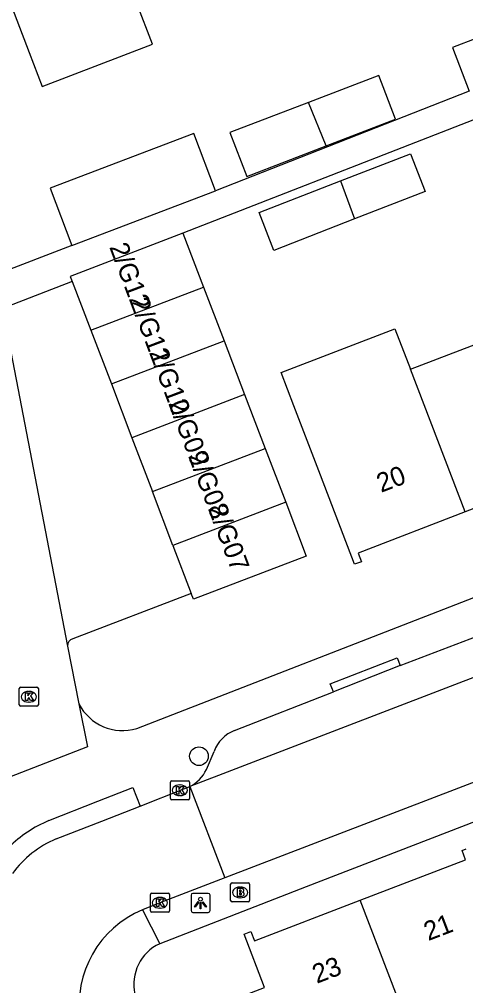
# Model space of a CAD drawing. Extents: x 159265 to 160143, y 383413 to 384319.
# Drawn here: x 159373.8 to 159397.2, y 383766.1 to 383816.8 of the extents above; entities that cross this region are included whole.
import ezdxf

# ---------------------------------------------------------------- set-up
doc = ezdxf.new("R2010")
doc.units = 0
for name, color, linetype in [('IMGEO_Boom', 7, 'Continuous'), ('IMGEO_Brandkraan', 7, 'Continuous'), ('IMGEO_Kolk', 7, 'Continuous'), ('IMGEO_Lichtpunt', 7, 'Continuous'), ('IMGEO_Pand', 7, 'Continuous'), ('IMGEO_Pand_nummerreeks', 7, 'Continuous'), ('IMGEO_Rijbaan_lokaal_open', 7, 'Continuous'), ('IMGEO_Voetpad_open', 7, 'Continuous')]:
    doc.layers.add(name, color=color, linetype=linetype)

msp = doc.modelspace()

# ---------------------------------------------------------------- linework, layer by layer
at = {"layer": 'IMGEO_Boom'}
msp.add_circle((159383.218, 383778.141), 0.489, dxfattribs=at)
at = {"layer": 'IMGEO_Brandkraan'}
for p, q in [((159384.953, 383771.497), (159385.805, 383771.497)), ((159384.878, 383770.571), (159384.878, 383771.423)), ((159385.366, 383771.277), (159385.391, 383771.277)), ((159385.879, 383771.423), (159385.879, 383770.571)), ((159385.805, 383770.497), (159384.953, 383770.497)), ((159385.389, 383770.717), (159385.364, 383770.717))]:
    msp.add_line(p, q, dxfattribs=at)
for points in [[(159384.953, 383771.497), (159385.805, 383771.497)], [(159384.878, 383770.571), (159384.878, 383771.423)], [(159385.226, 383771.197), (159385.226, 383770.797), (159385.439, 383770.797)], [(159385.457, 383771.197), (159385.226, 383771.197)], [(159385.405, 383771.116), (159385.351, 383771.116), (159385.351, 383771.04)], [(159385.351, 383771.04), (159385.404, 383771.04)], [(159385.879, 383771.423), (159385.879, 383770.571)], [(159385.805, 383770.497), (159384.953, 383770.497)], [(159385.413, 383770.964), (159385.351, 383770.964), (159385.351, 383770.883)], [(159385.351, 383770.883), (159385.413, 383770.883)]]:
    msp.add_lwpolyline(points, dxfattribs=at)
for centre, radius, start, end in [((159384.955, 383771.421), 0.0765, 91.552, 178.448), ((159384.955, 383771.421), 0.0765, 91.552, 178.448), ((159385.803, 383771.421), 0.0765, 1.552, 88.448), ((159385.803, 383771.421), 0.0765, 1.552, 88.448), ((159385.406, 383771.078), 0.0379, 267.8285, 90.9355), ((159385.461, 383771.052), 0.145, 59.4692, 91.5367), ((159385.486, 383771.099), 0.0922, 285.5137, 58.1501), ((159385.491, 383770.907), 0.105, 301.3115, 78.989), ((159384.955, 383770.573), 0.0765, 181.552, 268.448), ((159384.955, 383770.573), 0.0765, 181.552, 268.448), ((159385.414, 383770.923), 0.0404, 269.8759, 90.5077), ((159385.445, 383771.048), 0.251, 268.6676, 293.5347), ((159385.803, 383770.573), 0.0765, 271.552, 358.448), ((159385.803, 383770.573), 0.0765, 271.552, 358.448)]:
    msp.add_arc(centre, radius, start, end, dxfattribs=at)
for centre, major_axis, ratio, start_param, end_param in [((159385.365, 383770.997), (-0.387, 0.002), 0.722429, 4.712389, 7.853982), ((159385.39, 383770.997), (-0.39, 0.002), 0.717154, 1.570796, 4.712389)]:
    msp.add_ellipse(centre, major_axis=major_axis, ratio=ratio, start_param=start_param, end_param=end_param, dxfattribs=at)
at = {"layer": 'IMGEO_Kolk'}
for p, q in [((159373.785, 383780.835), (159373.785, 383781.687)), ((159373.86, 383781.761), (159374.712, 383781.761)), ((159374.786, 383781.687), (159374.786, 383780.835)), ((159374.273, 383781.541), (159374.298, 383781.541)), ((159374.712, 383780.761), (159373.86, 383780.761)), ((159374.296, 383780.981), (159374.271, 383780.981)), ((159381.718, 383775.927), (159381.718, 383776.779)), ((159381.793, 383776.853), (159382.645, 383776.853)), ((159382.206, 383776.633), (159382.231, 383776.633)), ((159382.719, 383776.779), (159382.719, 383775.927)), ((159382.229, 383776.073), (159382.204, 383776.073)), ((159382.645, 383775.853), (159381.793, 383775.853)), ((159380.668, 383770.026), (159380.668, 383770.878)), ((159380.743, 383770.952), (159381.595, 383770.952)), ((159381.156, 383770.732), (159381.181, 383770.732)), ((159381.669, 383770.878), (159381.669, 383770.026)), ((159381.179, 383770.172), (159381.154, 383770.172)), ((159381.595, 383769.952), (159380.743, 383769.952))]:
    msp.add_line(p, q, dxfattribs=at)
for points in [[(159373.785, 383780.835), (159373.785, 383781.687)], [(159373.86, 383781.761), (159374.712, 383781.761)], [(159374.786, 383781.687), (159374.786, 383780.835)], [(159374.106, 383781.461), (159374.229, 383781.461), (159374.229, 383781.31), (159374.359, 383781.461), (159374.523, 383781.461), (159374.377, 383781.31), (159374.53, 383781.061), (159374.378, 383781.061), (159374.293, 383781.225), (159374.229, 383781.158), (159374.229, 383781.061), (159374.106, 383781.061), (159374.106, 383781.461)], [(159374.712, 383780.761), (159373.86, 383780.761)], [(159381.718, 383775.927), (159381.718, 383776.779)], [(159381.793, 383776.853), (159382.645, 383776.853)], [(159382.039, 383776.553), (159382.162, 383776.553), (159382.162, 383776.402), (159382.292, 383776.553), (159382.456, 383776.553), (159382.31, 383776.402), (159382.463, 383776.153), (159382.311, 383776.153), (159382.226, 383776.317), (159382.162, 383776.25), (159382.162, 383776.153), (159382.039, 383776.153), (159382.039, 383776.553)], [(159382.719, 383776.779), (159382.719, 383775.927)], [(159382.645, 383775.853), (159381.793, 383775.853)], [(159380.668, 383770.026), (159380.668, 383770.878)], [(159380.743, 383770.952), (159381.595, 383770.952)], [(159380.989, 383770.652), (159381.112, 383770.652), (159381.112, 383770.501), (159381.242, 383770.652), (159381.406, 383770.652), (159381.26, 383770.501), (159381.413, 383770.252), (159381.261, 383770.252), (159381.176, 383770.416), (159381.112, 383770.349), (159381.112, 383770.252), (159380.989, 383770.252), (159380.989, 383770.652)], [(159381.669, 383770.878), (159381.669, 383770.026)], [(159381.595, 383769.952), (159380.743, 383769.952)]]:
    msp.add_lwpolyline(points, dxfattribs=at)
for centre, start, end in [((159373.862, 383781.685), 91.552, 178.448), ((159373.862, 383781.685), 91.552, 178.448), ((159374.71, 383781.685), 1.552, 88.448), ((159374.71, 383781.685), 1.552, 88.448), ((159373.862, 383780.837), 181.552, 268.448), ((159373.862, 383780.837), 181.552, 268.448), ((159374.71, 383780.837), 271.552, 358.448), ((159374.71, 383780.837), 271.552, 358.448), ((159381.795, 383776.777), 91.552, 178.448), ((159381.795, 383776.777), 91.552, 178.448), ((159382.643, 383776.777), 1.552, 88.448), ((159382.643, 383776.777), 1.552, 88.448), ((159381.795, 383775.929), 181.552, 268.448), ((159381.795, 383775.929), 181.552, 268.448), ((159382.643, 383775.929), 271.552, 358.448), ((159382.643, 383775.929), 271.552, 358.448), ((159380.745, 383770.876), 91.552, 178.448), ((159380.745, 383770.876), 91.552, 178.448), ((159381.593, 383770.876), 1.552, 88.448), ((159381.593, 383770.876), 1.552, 88.448), ((159380.745, 383770.028), 181.552, 268.448), ((159380.745, 383770.028), 181.552, 268.448), ((159381.593, 383770.028), 271.552, 358.448), ((159381.593, 383770.028), 271.552, 358.448)]:
    msp.add_arc(centre, 0.0765, start, end, dxfattribs=at)
for centre, major_axis, ratio, start_param, end_param in [((159374.272, 383781.261), (-0.387, 0.002), 0.722429, 4.712389, 7.853982), ((159374.297, 383781.261), (-0.39, 0.002), 0.717154, 1.570796, 4.712389), ((159382.205, 383776.353), (-0.387, 0.002), 0.722429, 4.712389, 7.853982), ((159382.23, 383776.353), (-0.39, 0.002), 0.717154, 1.570796, 4.712389), ((159381.155, 383770.452), (-0.387, 0.002), 0.722429, 4.712389, 7.853982), ((159381.18, 383770.452), (-0.39, 0.002), 0.717154, 1.570796, 4.712389)]:
    msp.add_ellipse(centre, major_axis=major_axis, ratio=ratio, start_param=start_param, end_param=end_param, dxfattribs=at)
at = {"layer": 'IMGEO_Lichtpunt'}
for p, q in [((159382.802, 383770.846), (159382.802, 383770.039)), ((159382.802, 383770.846), (159382.802, 383770.039)), ((159383.704, 383770.941), (159382.896, 383770.941)), ((159383.704, 383770.941), (159382.896, 383770.941)), ((159383.798, 383770.039), (159383.798, 383770.846)), ((159383.798, 383770.039), (159383.798, 383770.846)), ((159382.896, 383769.945), (159383.704, 383769.945)), ((159382.896, 383769.945), (159383.704, 383769.945))]:
    msp.add_line(p, q, dxfattribs=at)
for points in [[(159383.176, 383770.51), (159383.215, 383770.482), (159383.027, 383770.22), (159382.989, 383770.247), (159383.176, 383770.51)], [(159383.278, 383770.462), (159383.325, 383770.462), (159383.325, 383770.14), (159383.278, 383770.14), (159383.278, 383770.462)], [(159383.388, 383770.482), (159383.426, 383770.509), (159383.613, 383770.247), (159383.574, 383770.219), (159383.388, 383770.482)]]:
    msp.add_lwpolyline(points, dxfattribs=at)
msp.add_circle((159383.301, 383770.644), 0.0994, dxfattribs=at)
for centre, start, end in [((159382.896, 383770.846), 90, 180), ((159382.896, 383770.846), 90, 180), ((159383.704, 383770.846), 0, 90), ((159383.704, 383770.846), 0, 90), ((159382.896, 383770.039), 180, 270), ((159382.896, 383770.039), 180, 270), ((159383.704, 383770.039), 270, 0), ((159383.704, 383770.039), 270, 360)]:
    msp.add_arc(centre, 0.0946, start, end, dxfattribs=at)
at = {"layer": 'IMGEO_Pand'}
for points in [[(159377.252, 383825.293), (159371.658, 383823.154), (159371.496, 383823.577), (159371.098, 383823.424), (159374.298, 383815.054), (159374.978, 383813.275), (159380.773, 383815.492), (159379.954, 383817.632), (159380.153, 383817.708)], [(159400.367, 383816.796), (159396.531, 383815.33), (159397.412, 383813.025)], [(159389.903, 383810.156), (159393.539, 383811.56), (159392.655, 383813.849), (159388.968, 383812.44)], [(159388.968, 383812.44), (159384.836, 383810.86), (159385.724, 383808.56), (159389.903, 383810.156)], [(159389.903, 383810.156), (159388.968, 383812.44)], [(159384.09, 383807.808), (159382.941, 383810.816), (159375.402, 383807.935), (159376.551, 383804.927)], [(159390.648, 383808.322), (159394.32, 383809.752), (159395.092, 383807.77), (159391.389, 383806.328)], [(159391.389, 383806.328), (159387.155, 383804.679), (159386.383, 383806.661), (159390.648, 383808.322)], [(159390.648, 383808.322), (159391.389, 383806.328)], [(159376.551, 383804.927), (159384.09, 383807.808)], [(159382.374, 383805.575), (159376.461, 383803.316), (159376.563, 383803.049)], [(159382.374, 383805.575), (159383.454, 383802.753)], [(159376.563, 383803.049), (159377.54, 383800.491)], [(159377.54, 383800.491), (159383.454, 383802.753)], [(159383.454, 383802.753), (159384.533, 383799.932)], [(159377.54, 383800.491), (159378.618, 383797.669)], [(159397.195, 383790.954), (159391.571, 383788.797), (159391.744, 383788.346), (159391.387, 383788.209), (159389.597, 383792.878), (159388.2, 383796.52), (159387.528, 383798.271), (159393.506, 383800.567), (159394.321, 383798.443)], [(159394.321, 383798.443), (159400.132, 383800.675)], [(159378.618, 383797.669), (159384.533, 383799.932)], [(159384.533, 383799.932), (159385.613, 383797.11)], [(159397.195, 383790.954), (159394.321, 383798.443)], [(159378.618, 383797.669), (159379.696, 383794.847)], [(159385.613, 383797.11), (159379.696, 383794.847)], [(159385.613, 383797.11), (159386.692, 383794.288)], [(159379.696, 383794.847), (159380.774, 383792.024)], [(159380.774, 383792.024), (159386.692, 383794.288)], [(159386.692, 383794.288), (159387.772, 383791.467)], [(159403.182, 383792.726), (159402.996, 383792.655), (159402.821, 383793.111), (159397.195, 383790.954)], [(159381.852, 383789.202), (159380.774, 383792.024)], [(159387.772, 383791.467), (159381.852, 383789.202)], [(159387.772, 383791.467), (159388.851, 383788.645), (159382.929, 383786.384), (159382.814, 383786.685)], [(159381.852, 383789.202), (159382.814, 383786.685)], [(159391.678, 383770.585), (159397.219, 383772.712), (159397.031, 383773.199), (159397.25, 383773.283)], [(159382.7, 383750.83), (159394.45, 383755.134), (159391.879, 383761.875), (159389.07, 383760.801), (159389.22, 383760.409), (159388.866, 383760.273), (159388.72, 383760.653), (159385.981, 383759.602), (159383.927, 383764.958), (159386.663, 383766.007), (159385.588, 383768.807), (159385.945, 383768.945), (159386.133, 383768.456), (159391.678, 383770.585)], [(159395.493, 383760.684), (159394.619, 383762.923), (159391.678, 383770.585)]]:
    msp.add_lwpolyline(points, dxfattribs=at)
at = {"layer": 'IMGEO_Rijbaan_lokaal_open'}
for points in [[(159451.704, 383802.889), (159430.813, 383794.888), (159413.843, 383788.378), (159398.361, 383782.558), (159382.731, 383776.545)], [(159372.911, 383801.632), (159376.323, 383783.917)], [(159454.155, 383798.309), (159451.565, 383797.259), (159442.971, 383794.05), (159432.691, 383790.083), (159420.987, 383785.667), (159409.934, 383781.376), (159399.847, 383777.623), (159384.569, 383771.758)], [(159376.323, 383783.917), (159376.917, 383780.881)], [(159376.917, 383780.881), (159377.366, 383778.632), (159372.625, 383776.797)], [(159380.129, 383775.526), (159382.42, 383776.425), (159382.731, 383776.545)], [(159382.731, 383776.545), (159384.569, 383771.758)], [(159375.723, 383773.799), (159378.116, 383774.737), (159380.129, 383775.526)], [(159384.569, 383771.758), (159381.169, 383770.453), (159380.25, 383770.078)]]:
    msp.add_lwpolyline(points, dxfattribs=at)
for centre, radius, start, end in [((159377.845, 383768.747), 5.48, 112.7814, 143.7617), ((159382.299, 383765.115), 5.369, 112.4347, 188.5158)]:
    msp.add_arc(centre, radius, start, end, dxfattribs=at)
at = {"layer": 'IMGEO_Voetpad_open'}
for points in [[(159409.503, 383816.15), (159382.374, 383805.575)], [(159397.412, 383813.025), (159384.09, 383807.808)], [(159379.948, 383779.592), (159397.972, 383786.591), (159451.753, 383807.11)], [(159376.551, 383804.927), (159372.571, 383803.406)], [(159393.78, 383782.895), (159398.196, 383784.571), (159413.143, 383790.204), (159430.113, 383796.714), (159447.613, 383803.415)], [(159376.563, 383803.049), (159372.911, 383801.632)], [(159454.891, 383796.495), (159397.777, 383774.733), (159388.854, 383771.293), (159381.158, 383768.297)], [(159382.814, 383786.685), (159376.601, 383784.307)], [(159390.277, 383781.527), (159390.1, 383781.947), (159393.632, 383783.306), (159393.78, 383782.895)], [(159393.78, 383782.895), (159390.277, 383781.527)], [(159385.087, 383779.494), (159390.277, 383781.527)], [(159383.608, 383777.443), (159384.015, 383778.392)], [(159375.341, 383774.766), (159377.913, 383775.783), (159379.742, 383776.506), (159380.129, 383775.526)], [(159380.25, 383770.078), (159381.158, 383768.297)]]:
    msp.add_lwpolyline(points, dxfattribs=at)
for centre, radius, start, end in [((159376.686, 383783.952), 0.365, 103.479, 185.5569), ((159379.208, 383782.061), 2.577, 207.2432, 286.6794), ((159385.789, 383777.739), 1.89, 111.7958, 159.7854), ((159381.91, 383778.224), 1.869, 296.053, 335.3027), ((159377.833, 383768.762), 6.501, 112.5453, 135.085), ((159382.118, 383766.185), 2.32, 114.4344, 192.9764)]:
    msp.add_arc(centre, radius, start, end, dxfattribs=at)

# ---------------------------------------------------------------- texts
at = {"layer": 'IMGEO_Pand_nummerreeks'}
for s, rotation, p in [('2/G12', 290.6744, (159378.499, 383804.862)), ('2/G11', 290.6744, (159379.582, 383801.992)), ('2/G10', 290.6744, (159380.586, 383799.332)), ('2/G09', 290.6744, (159381.593, 383796.663)), ('2/G08', 290.6744, (159382.637, 383793.897)), ('20', 20.9359, (159392.78, 383791.957)), ('2/G07', 290.6744, (159383.678, 383791.139)), ('21', 20.9611, (159395.256, 383768.438)), ('23', 20.9611, (159389.406, 383766.198))]:
    msp.add_text(s, height=1, rotation=rotation, dxfattribs=at).set_placement(p)

doc.saveas('drawing.dxf')
